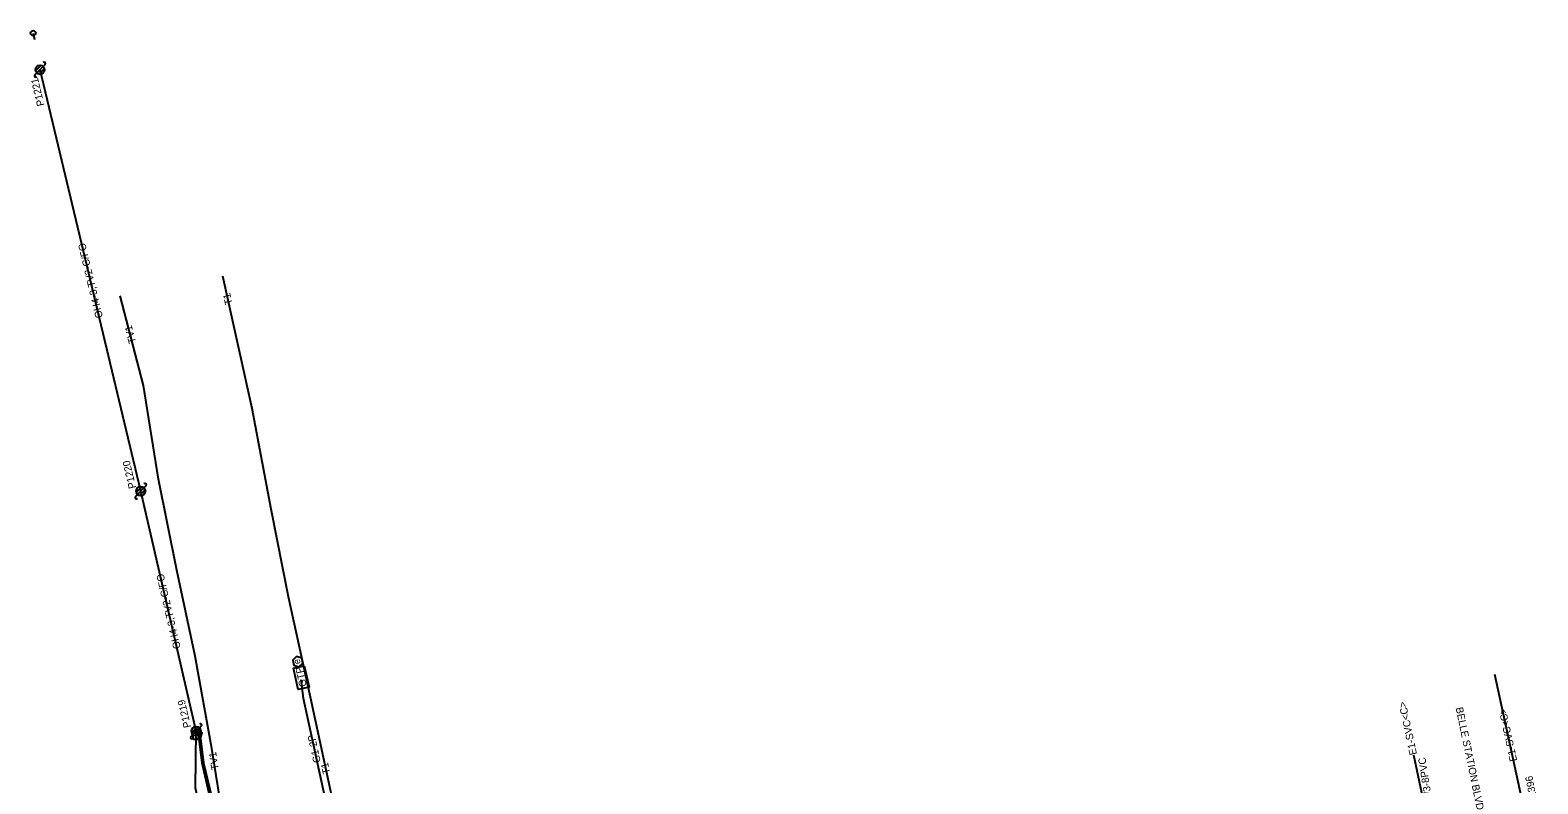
# Model space of a CAD drawing. Extents: x 2336688 to 2352634, y 362473 to 369571.
# Drawn here: x 2351064 to 2351881, y 369014 to 369422 of the extents above; entities that cross this region are included whole.
import ezdxf

# ---------------------------------------------------------------- set-up
doc = ezdxf.new("R2010")
doc.units = 0
for name, color, linetype in [('RD_EX_DV_Prop', 7, 'Continuous'), ('RD_EX_DV_TX_Prop', 7, 'Continuous'), ('RD_EX_RW', 7, 'Continuous'), ('RD_EX_RW_TX', 7, 'Continuous'), ('RD_HC_CL_Rel', 7, 'Continuous'), ('RD_HC_Data_Tic', 7, 'Continuous'), ('RD_PD_CstnLmt', 7, 'Continuous'), ('RD_PD_Final_TrvlWay', 7, 'Continuous'), ('RD_PD_PatLn2', 7, 'Continuous'), ('RD_PD_PatLn4', 7, 'Continuous'), ('RD_SHT_ShtClip', 7, 'Continuous'), ('RD_TX_Misc1', 7, 'Continuous')]:
    doc.layers.add(name, color=color, linetype=linetype)

# ---------------------------------------------------------------- blocks, each defined once
blk = doc.blocks.new('GW')
at = {"layer": 'RD_HC_Data_Tic'}
blk.add_line((0, 0), (0, 5), dxfattribs=at)
blk.add_circle((0, 0), 2, dxfattribs=at)

msp = doc.modelspace()

# ---------------------------------------------------------------- linework, layer by layer
at = {"layer": 'RD_EX_RW_TX'}
for points in [[(2351168.22, 369289), (2351184.03, 369217.25), (2351194.44, 369162.64), (2351203.85, 369115.24), (2351215.71, 369060.82), (2351227.21, 369007.22), (2351238.98, 368952.88), (2351250.05, 368899.81), (2351259.46, 368850.86), (2351264.5, 368840.05), (2351278.6, 368832.56), (2351284.45, 368830.16), (2351291.64, 368830.61)], [(2351198.76, 368823.01), (2351198.52, 368824.9), (2351198.25, 368836.21), (2351190.72, 368884.6), (2351179.85, 368933.22), (2351170.45, 368983.31), (2351162.38, 369032.96), (2351153.33, 369082.81), (2351143.41, 369129.58), (2351133.6, 369178.86), (2351125.36, 369229.59), (2351112.81, 369278.13)], [(2351153.96, 369042.26), (2351155.5, 369041.02), (2351157.29, 369024.92), (2351167.43, 368982.74), (2351177.7, 368932.89), (2351188.7, 368884.02), (2351193.83, 368853.61), (2351194.09, 368851.6)], [(2351153.96, 369042.26), (2351155.83, 369041.26), (2351157.97, 369025.19), (2351167.98, 368982.78), (2351178.11, 368932.9), (2351189.2, 368884.08), (2351194.47, 368853.53), (2351194.09, 368851.6)], [(2351153.96, 369042.26), (2351155.09, 369040.85), (2351156.91, 369025.02), (2351166.81, 368982.76), (2351177.17, 368932.66), (2351188.08, 368883.71), (2351193.27, 368853.33), (2351194.09, 368851.6)]]:
    msp.add_lwpolyline(points, dxfattribs=at)
at = {"layer": 'RD_HC_CL_Rel'}
for points in [[(2351208.36, 369082.75), (2351206.23, 369080.81), (2351206.84, 369077.99), (2351209.59, 369077.11), (2351211.73, 369079.05), (2351211.11, 369081.87)], [(2351212.52, 369077.75), (2351215.08, 369066.02), (2351209.21, 369064.75), (2351206.66, 369076.47)]]:
    msp.add_lwpolyline(points, close=True, dxfattribs=at)
msp.add_lwpolyline([(2351210.67, 369070.16), (2351211.87, 369060.2), (2351223.48, 369007.05)], dxfattribs=at)
at = {"layer": 'RD_HC_Data_Tic'}
for p, q in [((2351066.91, 369399.98), (2351069.97, 369403.04)), ((2351067.55, 369398.86), (2351071.09, 369402.4)), ((2351068.67, 369398.21), (2351071.73, 369401.28)), ((2351071.09, 369402.4), (2351072.15, 369403.46)), ((2351066.49, 369397.8), (2351067.55, 369398.86)), ((2351121.47, 369171.65), (2351124.53, 369174.71)), ((2351122.12, 369170.53), (2351125.65, 369174.07)), ((2351123.24, 369169.88), (2351126.3, 369172.95)), ((2351125.65, 369174.07), (2351126.71, 369175.13)), ((2351121.06, 369169.47), (2351122.12, 369170.53)), ((2351151.55, 369041.61), (2351154.61, 369044.67)), ((2351152.19, 369040.49), (2351155.73, 369044.02)), ((2351153.31, 369039.84), (2351156.37, 369042.9)), ((2351155.73, 369044.02), (2351156.79, 369045.08)), ((2351151.13, 369039.43), (2351152.19, 369040.49))]:
    msp.add_line(p, q, dxfattribs=at)
for centre in [(2351069.32, 369400.63), (2351123.88, 369172.3), (2351153.96, 369042.26)]:
    msp.add_circle(centre, 2.5, dxfattribs=at)
for centre, start, end in [((2351071.62, 369403.99), 315, 135), ((2351067.02, 369397.27), 135, 315), ((2351126.18, 369175.66), 315, 135), ((2351121.59, 369168.94), 135, 315), ((2351156.26, 369045.61), 315, 135), ((2351151.66, 369038.9), 135, 315)]:
    msp.add_arc(centre, 0.75, start, end, dxfattribs=at)
at = {"layer": 'RD_PD_Final_TrvlWay'}
msp.add_line((2351873.91, 368998.24), (2351857.57, 369073.04), dxfattribs=at)
msp.add_lwpolyline([(2351154.25, 369043.45), (2351151.34, 369041.34), (2351152.45, 369037.93), (2351156.04, 369037.93), (2351157.15, 369041.34)], close=True, dxfattribs=at)
msp.add_lwpolyline([(2351813.53, 369029.36), (2351821.49, 368992.14), (2351823.9, 368989.67), (2351794.62, 368950.67), (2351778.05, 368940.44), (2351775.15, 368938.78), (2351642.49, 368917.24), (2351514.5, 368883.56), (2351514.77, 368877.23), (2351511.62, 368882.8), (2351407.12, 368855.31), (2351405.59, 368848.58), (2351402.3, 368851.72), (2351332.34, 368833.32), (2351331.07, 368827.87)], dxfattribs=at)
at = {"layer": 'RD_SHT_ShtClip'}
for p, q in [((2351123.88, 369172.3), (2351069.32, 369400.63)), ((2351153.96, 369042.26), (2351123.88, 369172.3))]:
    msp.add_line(p, q, dxfattribs=at)
msp.add_lwpolyline([(2351194.09, 368851.6), (2351181.3, 368879.57), (2351153.53, 369011.51), (2351153.96, 369042.26)], dxfattribs=at)

# ---------------------------------------------------------------- block references
at = {"layer": 'RD_HC_Data_Tic', "xscale": 0.6933464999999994, "yscale": 0.6933464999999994, "rotation": -169.04017559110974}
msp.add_blockref('GW', (2351065.59, 369420.44), dxfattribs=at)

# ---------------------------------------------------------------- texts
at = {"layer": 'RD_EX_DV_Prop'}
for rotation, p in [(102.0785, (2351815.48, 369029.78)), (102.24842, (2351869.78, 369026.3))]:
    msp.add_text('E1-SVC<C>', height=4, rotation=rotation, dxfattribs=at).set_placement(p)
at = {"layer": 'RD_EX_DV_TX_Prop'}
for s, rotation, p in [('P1221', 103.44015, (2351071.74, 369381.41)), ('P1220', 103.44015, (2351121.43, 369174.18)), ('P1219', 103.02193, (2351151.17, 369044.55)), ('P1396', 101.67916, (2351881.04, 369003.19))]:
    msp.add_text(s, height=4, rotation=rotation, dxfattribs=at).set_placement(p)
at = {"layer": 'RD_EX_RW'}
for s, rotation, p in [('T1', 102.42544, (2351173.62, 369273.81)), ('TV1', 104.49185, (2351121.39, 369252.91)), ('TV1', 99.2305, (2351166.25, 369021.6)), ('T1', 102.11067, (2351226.63, 369019.46))]:
    msp.add_text(s, height=4, rotation=rotation, dxfattribs=at).set_placement(p)
at = {"layer": 'RD_HC_CL_Rel'}
for s, height, p in [('e', 3.75, (2351210.63, 369078.94)), ('GTP', 4, (2351213.9, 369066.72))]:
    msp.add_text(s, height=height, rotation=102.28636, dxfattribs=at).set_placement(p)
at = {"layer": 'RD_PD_CstnLmt'}
msp.add_text('W3-8PVC', height=4, rotation=98.9821, dxfattribs=at).set_placement((2351823.7, 369004.82))
at = {"layer": 'RD_PD_Final_TrvlWay'}
msp.add_text('E', height=3.75, dxfattribs=at).set_placement((2351153.13, 369038.41))
at = {"layer": 'RD_PD_PatLn2'}
msp.add_text('G1-2P', height=4, rotation=102.32124, dxfattribs=at).set_placement((2351221.48, 369025.56))
at = {"layer": 'RD_PD_PatLn4'}
for rotation, p in [(103.44015, (2351103.42, 369266.55)), (103.02193, (2351145.59, 369087.32))]:
    msp.add_text('OH4-3,TV2-C/FO', height=4, rotation=rotation, dxfattribs=at).set_placement(p)
at = {"layer": 'RD_TX_Misc1'}
msp.add_text('BELLE STATION BLVD', height=4, rotation=281.72851, dxfattribs=at).set_placement((2351836.4, 369054.85))

doc.saveas('drawing.dxf')
